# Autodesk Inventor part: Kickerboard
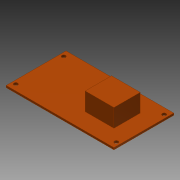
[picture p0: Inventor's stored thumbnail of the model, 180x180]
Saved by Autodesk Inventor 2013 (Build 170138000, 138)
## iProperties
Created: 2012-08
Part Number: Kickerboard
Material: Phenolharz
Document SubType Name: Modeling
Designer: rYan
Mass: 20.7946 g
Surface Area: 108.28 cm^2
Volume: 15.0685 cm^3
Density: 1.38 g/cm^3
Author: rYan
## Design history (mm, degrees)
sketch "Skizze1"
  geometry: L1 (-45, 25)-(45, 25); L2 (45, 25)-(45, -25); L3 (45, -25)-(-45, -25); L4 (-45, -25)-(-45, 25); L5 (0, 35)-(0, -35) reference; L6 (-63, 0)-(63, 0) reference; 1 further point
  constraints: 8 end point, 2 parallel, 1 horizontal, 1 perpendicular, 2 other
  dimensions: "d0" = 90 distance of L1.start L1.end; "d1" = 50 distance of L3.end L1.start
extrude "Extrusion1" new body sketch "Skizze1" distance "d2" = 1.6; taper "d3" = 0 deg
sketch "Skizze2"
  geometry: L1 (7, 11)-(31, 11); L2 (31, 11)-(31, -11); L3 (31, -11)-(7, -11); L4 (7, -11)-(7, 11); L5 (-63, 0)-(63, 0) reference; L6 (45, -25)-(45, 25) reference; 1 further point
  constraints: 8 end point, 2 parallel, 1 horizontal, 1 perpendicular, 1 other
  dimensions: "d4" = 22 distance of L3.end L1.start; "d6" = 24 distance of L1.start L1.end; "d7" = 14 distance between parallel lines of L6 L2
extrude "Extrusion2" join sketch "Skizze2" distance "d8" = 15; taper "d9" = 0 deg
sketch "Skizze3"
  geometry: L1 (45, 25)-(-45, 25) reference; L2 (-45, -25)-(-45, 25) reference; 2 further points
  dimensions: "d10" = 5 distance from line of L1 point (-42, 20); "d11" = 3 distance from line of L2 point (-42, 20)
hole "Bohrung1" sketch "Skizze3" at (-42, 20) diameter "d12" = 3.2; stored, may be unused: countersink angle "d16" = 90 deg, drill point angle "d18" = 118 deg; dims "d13" = 6, "d14" = 4, "d15" = 2, "d17" = 8
pattern_linear "Rechteckige Anordnung1" dims "d21" = 84
node "Volumenkörper1"
